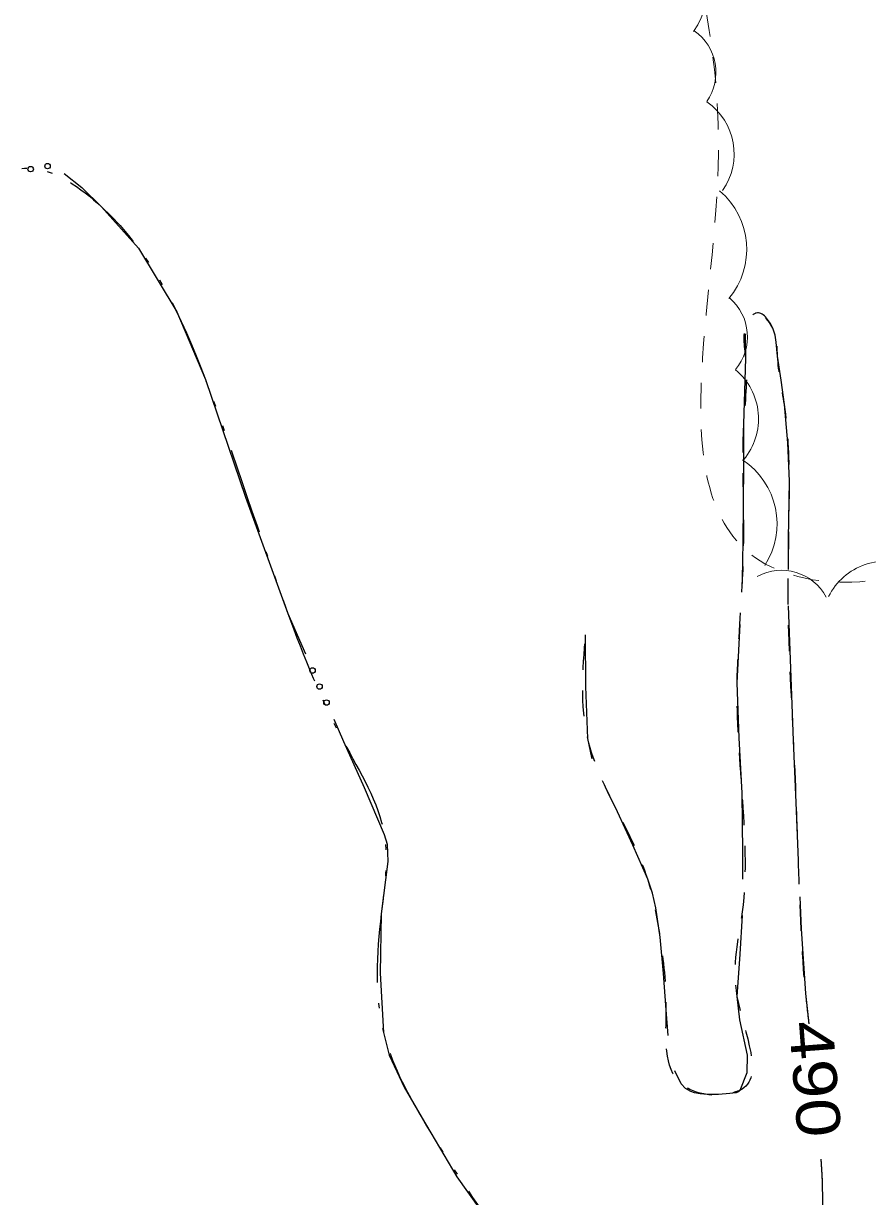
# Model space of a CAD drawing. Extents: x 2362213 to 2366494, y 6968794 to 6978110.
# Drawn here: x 2364129.4 to 2364222.2, y 6970115.9 to 6970244.9 of the extents above; entities that cross this region are included whole.
import ezdxf
from ezdxf.enums import TextEntityAlignment as Align

# ---------------------------------------------------------------- set-up
doc = ezdxf.new("R2010")
doc.units = 0
doc.header["$LTSCALE"] = 1.9
doc.linetypes.add('DASH_DOUBLE_DOT', pattern=[9.2, 5, -1.2, 0.3, -1.2, 0.3, -1.2])
doc.linetypes.add('SHORT_DASHED', pattern=[2.7, 1.5, -1.2])
for name, color, linetype, lineweight in [('25', 7, 'Continuous', 25), ('29', 7, 'Continuous', 13), ('31', 7, 'Continuous', 25), ('32', 7, 'Continuous', 25)]:
    doc.layers.add(name, color=color, linetype=linetype, lineweight=lineweight)

msp = doc.modelspace()

# ---------------------------------------------------------------- linework, layer by layer
at = {"layer": '25'}
for points in [[(2364133.862, 6970228.4), (2364135.807, 6970226.869), (2364137.977, 6970224.749), (2364142.05, 6970220.187), (2364146.287, 6970213.208), (2364149.408, 6970205.767), (2364153.822, 6970192.828), (2364158.474, 6970180.032), (2364160.406, 6970175.579)], [(2364163.525, 6970168.389), (2364164.598, 6970165.93), (2364166.877, 6970160.881), (2364169.086, 6970155.702), (2364169.386, 6970154.644), (2364169.484, 6970152.755), (2364168.749, 6970146.978), (2364168.631, 6970140.457), (2364168.993, 6970133.95), (2364169.617, 6970131.455), (2364171.27, 6970127.931), (2364173.253, 6970124.5), (2364177.075, 6970118.047), (2364180.764, 6970112.862)]]:
    msp.add_lwpolyline(points, dxfattribs=at)
for centre in [(2364130.194, 6970228.888), (2364132.048, 6970229.216), (2364161.2, 6970173.747), (2364161.964, 6970171.986), (2364162.73, 6970170.226)]:
    msp.add_circle(centre, 0.3, dxfattribs=at)
at = {"layer": '25', "linetype": 'DASH_DOUBLE_DOT'}
msp.add_spline([(2364036.681, 6970273.237), (2364041.679, 6970269.174), (2364051.363, 6970258.226), (2364054.142, 6970254.152), (2364056.675, 6970247.666), (2364053.195, 6970235.942), (2364047.149, 6970225.154), (2364046.431, 6970214.416), (2364059.059, 6970198.975), (2364084.23, 6970200.046), (2364102.328, 6970210.839), (2364117.451, 6970221.073), (2364130.366, 6970228.987), (2364137.977, 6970224.749), (2364149.408, 6970205.767), (2364158.474, 6970180.032), (2364164.598, 6970165.93), (2364169.086, 6970155.702), (2364168.749, 6970146.978), (2364168.993, 6970133.95), (2364173.253, 6970124.5), (2364181.423, 6970111.928)], degree=3, dxfattribs=at)
at = {"layer": '29'}
for centre, radius, start, end in [((2364196.207, 6970248.838), 8.404, 325.0741, 55.0741), ((2364199.965, 6970239.521), 5.599, 325.0741, 55.0741), ((2364200.553, 6970230.546), 7.006, 325.0741, 55.0741), ((2364200.544, 6970220.071), 8.404, 319.81196, 49.81196), ((2364203.432, 6970210.448), 5.599, 319.81196, 49.81196), ((2364203.238, 6970201.425), 7.006, 320.23346, 50.23346), ((2364203.88, 6970189.87), 8.404, 326.9344, 56.9344), ((2364224.218, 6970178.757), 7.006, 63.54578, 153.54578), ((2364212.762, 6970179.169), 5.599, 28.27647, 118.27647)]:
    msp.add_arc(centre, radius, start, end, dxfattribs=at)
at = {"layer": '29', "linetype": 'SHORT_DASHED'}
msp.add_spline([(2363819.747, 6970158.026), (2363833.428, 6970176.986), (2363859.818, 6970191.748), (2363889.175, 6970213.148), (2363902.004, 6970241.742), (2363923.176, 6970262.634), (2363951.045, 6970272.321), (2363972.181, 6970282.342), (2363989.376, 6970285.026), (2364009.131, 6970284.544), (2364040.025, 6970289.639), (2364067.833, 6970297.314), (2364089.729, 6970309.363), (2364116.874, 6970334.123), (2364142.838, 6970357.901), (2364162.086, 6970364.585), (2364191.414, 6970361.824), (2364204.329, 6970351.877), (2364204.017, 6970346.834), (2364196.865, 6970314.464), (2364198.103, 6970273.714), (2364205.818, 6970229.125), (2364210.955, 6970185.492), (2364223.99, 6970183.886), (2364240.264, 6970197.181), (2364241.582, 6970237.316), (2364247.956, 6970246.327), (2364255.782, 6970226.971), (2364254.29, 6970183.115), (2364251.704, 6970145.778), (2364250.854, 6970111.088)], degree=3, dxfattribs=at)
at = {"layer": '32'}
for points in [[(2364213.53, 6970184.847), (2364213.548, 6970188.237), (2364213.638, 6970194.557), (2364213.478, 6970198.776), (2364213.098, 6970202.993), (2364212.733, 6970205.66), (2364212.338, 6970208.316), (2364212.203, 6970209.865), (2364212.086, 6970210.634), (2364211.818, 6970211.402), (2364211.453, 6970212.008), (2364211.109, 6970212.425), (2364211.058, 6970212.464)], [(2364208.793, 6970210.783), (2364208.819, 6970208.093), (2364208.693, 6970204.462), (2364208.598, 6970200.821), (2364208.58, 6970196.419), (2364208.572, 6970192.009), (2364208.531, 6970187.899), (2364208.46, 6970183.798), (2364208.4, 6970182.788)], [(2364214.635, 6970152.865), (2364214.374, 6970159.234), (2364214.109, 6970166.051), (2364213.804, 6970173.978), (2364213.548, 6970180.847)], [(2364208.178, 6970178.796), (2364208.144, 6970178.095), (2364207.858, 6970172.401), (2364208.096, 6970166.334), (2364208.414, 6970160.267), (2364208.496, 6970153.736), (2364208.474, 6970150.816)], [(2364191.957, 6970164.05), (2364191.906, 6970164.17), (2364191.456, 6970166.286), (2364191.252, 6970171.973), (2364191.218, 6970177.674)], [(2364200.308, 6970133.599), (2364200.101, 6970136.427), (2364199.803, 6970140.424), (2364199.435, 6970144.421), (2364198.944, 6970147.655), (2364198.569, 6970149.252), (2364198.054, 6970150.807), (2364196.428, 6970154.522), (2364194.753, 6970158.197), (2364193.632, 6970160.426)], [(2364215.816, 6970134.906), (2364215.62, 6970136.564), (2364215.444, 6970138.223), (2364214.977, 6970145.318), (2364214.813, 6970148.866)], [(2364208.432, 6970146.816), (2364208.203, 6970142.544), (2364207.877, 6970137.891), (2364208.152, 6970135.313), (2364209.009, 6970131.44), (2364208.957, 6970129.51), (2364208.185, 6970127.572), (2364208.087, 6970127.451), (2364207.977, 6970127.37), (2364207.778, 6970127.298), (2364207.089, 6970127.232), (2364205.85, 6970127.1), (2364204.61, 6970127.108), (2364203.819, 6970127.191), (2364203.218, 6970127.305), (2364202.796, 6970127.441), (2364202.213, 6970127.775), (2364201.728, 6970128.291), (2364201.055, 6970129.704)], [(2364217.307, 6970112.739), (2364217.324, 6970115.2), (2364217.27, 6970117.649), (2364217.219, 6970118.819), (2364217.138, 6970119.988)]]:
    msp.add_lwpolyline(points, dxfattribs=at)
at = {"layer": '32', "linetype": 'SHORT_DASHED'}
for points in [[(2364215.816, 6970134.906), (2364215.444, 6970138.223), (2364214.649, 6970152.425), (2364214.109, 6970166.051), (2364213.508, 6970181.916), (2364213.638, 6970194.557), (2364213.098, 6970202.993), (2364212.338, 6970208.316), (2364211.818, 6970211.402), (2364209.992, 6970213.064), (2364209.06, 6970212.125), (2364208.819, 6970208.093), (2364208.598, 6970200.821), (2364208.572, 6970192.009), (2364208.46, 6970183.798), (2364207.858, 6970172.401), (2364208.414, 6970160.267), (2364208.448, 6970147.206), (2364207.877, 6970137.891), (2364208.185, 6970127.572), (2364207.089, 6970127.232), (2364204.61, 6970127.108), (2364201.728, 6970128.291), (2364200.101, 6970136.427), (2364199.435, 6970144.421), (2364198.054, 6970150.807), (2364194.753, 6970158.197), (2364191.456, 6970166.286), (2364191.218, 6970177.674)], [(2364217.307, 6970112.739), (2364217.27, 6970117.649), (2364217.138, 6970119.988)]]:
    msp.add_spline(points, degree=3, dxfattribs=at)

# ---------------------------------------------------------------- texts
at = {"layer": '31', "width": 1.2}
msp.add_text(' 490 ', height=4.8, rotation=274.336, dxfattribs=at).set_placement((2364214.082, 6970128.655), align=Align.CENTER)

doc.saveas('drawing.dxf')
